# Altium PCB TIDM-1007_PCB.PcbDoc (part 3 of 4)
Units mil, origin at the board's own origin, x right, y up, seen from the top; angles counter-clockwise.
Board outline 9645.67 x 3346.46 mil, 6 copper layers (Top Layer, Signal Layer 1, Signal Layer 2, Signal Layer 3, Signal Layer 4, Bottom Layer), stack 60.2 mil thick; 189 components, 109 nets, 620 pads, 278 vias.
Unrouted connection lines stored in the file: 5.
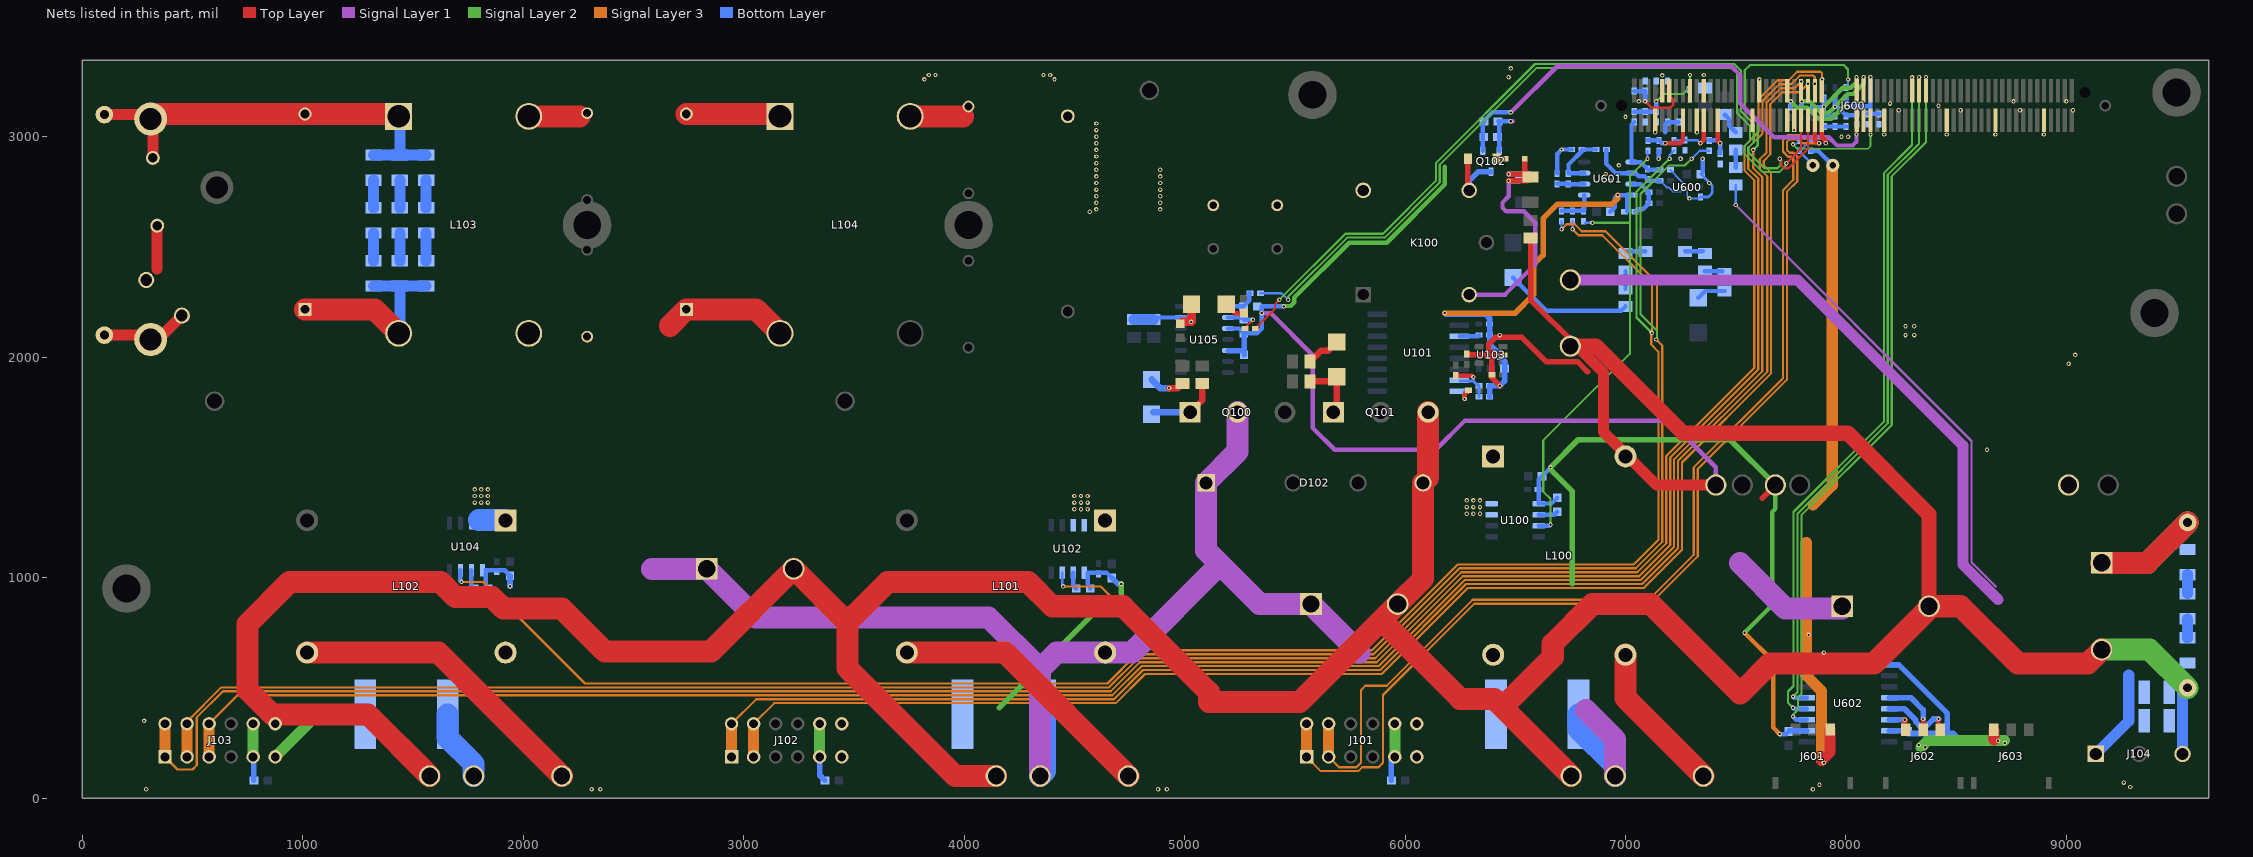
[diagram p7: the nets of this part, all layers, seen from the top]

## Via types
v1: diameter 20, hole 10, Top Layer to Bottom Layer, 278 vias

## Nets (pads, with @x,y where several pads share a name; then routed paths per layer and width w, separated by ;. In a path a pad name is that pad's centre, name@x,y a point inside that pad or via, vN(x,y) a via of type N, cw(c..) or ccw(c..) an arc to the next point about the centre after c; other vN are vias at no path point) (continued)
GAN_F3: J103.3 R626.2 | length 10076.2
  Signal Layer 2 w10: v1(7580,2940) 7600,2960 7600,3065.1 7541.38,3123.72 7541.38,3301.38 7565.49,3325.49 7989.5,3325.49 8009.72,3305.27 v1(8009.72,3259.37)
  Signal Layer 3 w10: J103.3@575,337 704.38,466.38 4672.21,466.38 4804.34,598.5 5879.61,598.5 6269.61,988.5 7068.5,988.5 7220.63,1140.63 7220.63,1537.02 7620,1936.39 7620,2817.44 7580,2857.44 v1(7580,2940)
  Signal Layer 3 w50: J103.3@575,187 J103.3@575,337
  Bottom Layer w10: R626.2@8000,3223.62 8009.72,3233.34 v1(8009.72,3259.37)
HVBUS: C100.1 C101.1 C102.1 C103.1 C104.2 C105.2 C106.2 C117.2 C126.2 D102.1 J104.1 L100.4 L101.2 L102.2 Q100.2 R129.2 R602.2 TP100.1 TP104.1 TP107.1 TP110.1 TP600.1 | length 13405.7
  Top Layer w100: C100.1@9160,1066.85 9366.85,1066.85 TP100.1@9550,1250
  Signal Layer 1 w10: v1(7500,2690) 8570,1620 8570,1070 8680,960
  Signal Layer 1 w50: TP600.1@6750,2350 7780,2350 8530,1600 8530,1060 8690,900
  Signal Layer 1 w100: 2585.28,1040 C103.1@2833.15,1040 3053.15,820 4110,820 4345,585 ; TP107.1@4345,100 4345,585 ; Q100.2@5240,1750 5240,1572.13 D102.1@5097.87,1430 5097.87,1123.15 5161.02,1060 ; 5793.15,660 C102.1@5573.15,880 5341.02,880 5161.02,1060 ; 6820,400 6953.45,266.55 TP104.1@6953.45,100 ; 7520,1065.28 7725.28,860 C101.1@7983.15,860 ; 4345,585 4420,660 L101.2@4640,660 4761.02,660 5161.02,1060
  Signal Layer 2 w100: C100.1@9160,1066.85 9366.85,1066.85 TP100.1@9550,1250
  Bottom Layer w10: v1(7500,2690) R602.2@7500,2780
  Bottom Layer w50: J104.1@9133.15,200 9282.91,349.76 9282.91,557.09
  Bottom Layer w100: C106.2@1657.01,380 1657.01,272.99 1775,155 TP110.1@1775,100 ; TP107.1@4345,100 4367.01,122.01 C117.2@4367.01,380 ; C126.2@6787.01,380 6787.01,312.99 6953.45,146.55 TP104.1@6953.45,100
L100_CS: R600.1 R627.2 U100.7 | length 2162.5
  Signal Layer 2 w10: v1(6660,1240) 6660,1357.1 6627.1,1390 6627.1,1622.37 7020,2015.28 7020,2610 ; v1(6850,2610) 7020,2610 ; v1(7100,2900) 7020,2820 7020,2610
  Bottom Layer w10: R627.2@6816.38,2610 v1(6850,2610) ; v1(7100,2900) R600.1@7100,2934.57
  Bottom Layer w20: U100.7@6607.28,1235 6655,1235 v1(6660,1240)
L101_CS: R603.1 R628.2 U102.7 | length 5690
  Signal Layer 2 w10: v1(7120,2110) 7050,2180 7050,2750 v1(7200,2900)
  Signal Layer 3 w10: v1(4450,960) 4620,960 4910,670 5850,670 6240,1060 7038.89,1060 7149.13,1170.24 7149.13,2025.12 7117.13,2057.13 7117.13,2107.13 v1(7120,2110) 7120,2327.87 6895,2552.87 6787.13,2552.87 v1(6760,2580)
  Bottom Layer w10: U102.7@4445,1022.72 4445,965 v1(4450,960) ; v1(6760,2580) R628.2@6760,2616.38 ; v1(7200,2900) 7200,2916.45 R603.1@7220,2936.45
L102_CS: R608.1 R629.2 U104.7 | length 8815.7
  Signal Layer 2 w10: v1(7140,2080) 7142.87,2082.87 7142.87,2119.47 7067.87,2194.47 7067.87,2739.69 7198.19,2870 7270,2870 v1(7300,2900)
  Signal Layer 3 w10: v1(1720,980.32) 1819.68,980.32 2280,520 4650,520 4782.13,652.13 5857.4,652.13 6247.4,1042.13 7046.29,1042.13 7167.01,1162.84 7167.01,2052.99 v1(7140,2080) ; v1(6710,2580) 6732.87,2602.87 6769.47,2602.87 6801.6,2570.75 6909.25,2570.75 7142.87,2337.13 v1@7142.87,2082.87
  Bottom Layer w10: v1(6710,2580) R629.2@6710,2616.38 ; v1(7300,2900) 7336.38,2936.38 R608.1@7380,2936.38
  Bottom Layer w20: U104.7@1715,1033.03 1715,985.32 v1(1720,980.32)
NetC107_1: C107.1 C110.1 L103.3 L104.2 | length 575.6
  Top Layer w100: 2665.28,2142.36 C110.1@2740,2217.09 3055.51,2217.09 L104.2@3164.72,2107.87
NetC109_1: C109.1 F100.1 L103.2 R105.2 R106.2 R107.2 RV100.2 | length 1116.4
  Top Layer w50: 339.8,2399.8 RV100.2@339.8,2596.45
  Top Layer w100: C109.1@1010,2217.09 1325.51,2217.09 L103.2@1434.72,2107.87
  Bottom Layer w50: R106.2@1320,2322.91 R107.2@1440,2322.91 ; L103.2@1440,2113.15 R107.2@1440,2322.91 ; R105.2@1560,2322.91 R107.2@1440,2322.91
NetC109_2: C109.2 L103.1 pad.0@310,3080 R111.1 R112.1 R113.1 RV100.1 TP103.1 | length 1889.4
  Top Layer w50: TP103.1@100,3100 pad.0@290,3100 ; RV100.1@320.2,2903.55 pad.0@320.2,3069.8
  Top Layer w100: pad.0@310,3080 332.91,3102.91 C109.2@1010,3102.91 L103.1@1423.94,3102.91
  Bottom Layer w50: R112.1@1320,2917.09 R113.1@1440,2917.09 ; L103.1@1440,3086.85 R113.1@1440,2917.09 ; R111.1@1560,2917.09 R113.1@1440,2917.09
NetC110_2: C110.2 C112.2 L103.4 L104.1 | length 644.2
  Top Layer w100: L103.4@2025.28,3092.13 2255.51,3092.13 ; C110.2@2740,3102.91 L104.1@3153.94,3102.91
NetC113_1: C113.1 C114.2 K100.2 L104.4 RT100.1 RT101.1 | length 240.2
  Top Layer w100: L104.4@3755.28,3092.13 3995.51,3092.13
  other v1: 4570,2660 4600,2670 4890,2670 4600,2700 4890,2700 4600,2730 4890,2730 4600,2760 4890,2760 4600,2790 4890,2790 4600,2820 4890,2820 4600,2850 4890,2850 4600,2880 4600,2910 4600,2940 4600,2970 4600,3000 4600,3030 4600,3060 3820,3260 4410,3260 3840,3280 3870,3280 4360,3280 4390,3280
NetC116_1: C116.1 U100.6 | length 88.3
  Bottom Layer w20: U100.6@6607.28,1285 6676.5,1285 C116.1@6690,1298.5
NetC124_1: C124.1 R117.1 R124.2 U101.15 | length 253.2
  Top Layer w20: R117.1@6230,1916.38 6303.62,1916.38 v1(6310,1910)
  Bottom Layer w14: U101.15@6250.01,1892 6310,1892 ; v1(6310,1910) 6310,1892 ; C124.1@6331.38,1875 C124.1@6336.38,1870 ; R124.2@6336.38,1820 C124.1@6336.38,1870 ; 6310,1892 6332,1870 C124.1@6336.38,1870
NetC125_1: C125.1 U102.6 | length 78.3
  Bottom Layer w20: U102.6@4495,1022.72 4495,963.51 C125.1@4508.5,950
NetC127_1: C127.1 U101.11 | length 91.4
  Bottom Layer w20: U101.11@6247.01,2095 6331.38,2095 C127.1@6336.38,2100
NetC134_1: C134.1 U104.6 | length 69.2
  Bottom Layer w20: C134.1@1765,963.82 U104.6@1765,1033.03
NetC135_1: C135.1 C137.1 C138.2 D107.1 U105.13 | length 392.3
  Top Layer w20: C138.2@4980,2151.5 C138.2@4988.5,2160
  Top Layer w39.37: C138.2@4988.5,2160 v1(5030,2160) 5031.26,2161.26 D107.1@5031.26,2240
  Bottom Layer w20: C135.1@4870,2180 U105.13@4982.72,2180 5010,2180 v1(5030,2160)
  Bottom Layer w50: C137.1@4770,2170 C135.1@4860,2170
NetC139_1: C139.1 R127.1 U105.1 | length 144.2
  Bottom Layer w20: U105.1@5197.28,2230 C139.1@5267.05,2230 5292.48,2255.43 5292.48,2290 R127.1@5296.38,2290
NetC140_1: C140.1 R128.1 U105.2 | length 172.1
  Top Layer w10: R128.1@5273.27,2130 5273.27,2133.27 v1(5310,2170)
  Bottom Layer w20: U105.2@5197.28,2180 5259.84,2180 C140.1@5268.35,2171.5 5269.84,2170 v1(5310,2170)
NetC601_1: C601.1 J600.15 R600.2 | length 261.2
  Top Layer w20: v1(7180.39,2970) 7248.19,2970 7260.91,2982.72 J600.15@7260.91,3073.94
  Bottom Layer w20: R600.2@7101.81,2983.62 C601.1@7151.81,2983.62 7165.43,2970 v1(7180.39,2970)
NetC603_2: C603.2 J600.12 R604.1 | length 310.5
  Top Layer w12: v1@7090,3160 7118.19,3131.81 7203.81,3131.81 7216.13,3144.13 7216.13,3167.64 7197.91,3185.85 J600.12@7197.91,3207.8
  Bottom Layer w20: R604.1@7040,3206.38 C603.2@7090,3206.38 v1@7090,3160
  other v1: 7089,3160
NetC604_1: C604.1 J600.21 R603.2 | length 236
  Top Layer w20: v1(7340,2970) 7355.39,2985.39 J600.21@7355.39,3073.94
  Bottom Layer w10: R603.2@7220,2983.69 7326.31,2983.69 v1(7340,2970)
NetC607_1: C607.1 J600.25 R608.2 | length 210.8
  Top Layer w20: J600.25@7418.39,3073.94 7418.39,2981.61 v1(7430,2970)
  Bottom Layer w20: R608.2@7380,2983.62 7416.38,2983.62 v1(7430,2970) C607.1@7430,2923.62
NetC608_1: C608.1 J600.18 R611.1 R613.2 | length 370.2
  Signal Layer 2 w10: v1(7140,3160) 7173.51,3193.51 7260,3193.51 7292.5,3226.01 v1(7292.5,3280)
  Bottom Layer w20: R611.1@7040,3113.62 R613.2@7090,3113.62 C608.1@7140,3113.62 7140,3150
NetC611_1: C611.1 J600.58 R618.1 R621.1 R631.2 | length 395.3
  Signal Layer 2 w20: v1(7900,3135.91) 7985.75,3221.65 8021.65,3221.65 8048,3248 v1(8048,3270)
  Bottom Layer w20: R618.1@7847.97,3133.62 v1@7897.72,3133.62 ; C611.1@7900,3095.43 v1(7900,3135.91) R621.1@7900,3176.38 ; C611.1@7901.81,3093.62 R631.2@7950,3093.62
NetC612_1: C612.1 J600.60 R620.1 R625.1 R632.2 | length 570
  Signal Layer 2 w20: v1(7800,3160) 7818.47,3160 7818.76,3159.71 7836.77,3159.71 7888.45,3108.03 7922.13,3108.03 v1(7950,3135.91) 8007.87,3193.78 8033.2,3193.78 8080,3240.58 v1(8080,3270)
  Bottom Layer w20: R620.1@7800,3135.65 v1(7800,3160) ; R625.1@7950,3176.38 v1(7950,3135.91) 7960.55,3135.91 8000,3096.46 8042.84,3096.46 R632.2@8050,3103.62
NetC613_1: C613.1 J600.62 R624.1 R626.1 R633.2 | length 685.2
  Signal Layer 2 w20: v1(7750,3160) 7778.16,3131.84 7825.23,3131.84 7876.91,3080.16 7933.67,3080.16 7987.61,3134.09 v1(8001.81,3134.09)
  Bottom Layer w20: R624.1@7750,3135.65 v1(7750,3160) ; R626.1@8001.81,3174.57 v1(8001.81,3134.09) 8004.96,3137.24 8108.24,3137.24 ; C613.1@8100,3103.62 R633.2@8150,3103.62 ; C613.1@8111,3114.62 v1(8111,3270)
NetC614_1: C614.1 R619.1 R622.1 U601.7 | length 261.1
  Bottom Layer w20: C614.1@6803.62,2936.22 6741.38,2873.97 6741.38,2835 U601.7@6812.72,2835 ; C614.1@6803.62,2941.81 R619.1@6866.38,2941.81
NetD100_1: D100.1 R102.2 | length 132.9
  Bottom Layer w20: D100.1@7330,2268.74 7361.26,2300 R102.2@7450,2300
NetD101_1: D101.1 R103.1 | length 164.3
  Top Layer w29.53: v1(4930,1860) 4970,1860 R103.1@4990,1880
  Bottom Layer w29.53: D101.1@4850,1898.74 4888.74,1860 v1(4930,1860)
NetD101_2: D101.2 Q100.1 R104.1 | length 319
  Top Layer w29.53: Q100.1@5025,1750 5080,1805 R104.1@5080,1880
  Bottom Layer w29.53: D101.2@4858.74,1750 Q100.1@5025,1750
NetD103_1: D103.1 R114.1 | length 156.8
  Top Layer w29.53: R114.1@5570,1980 5620,2030 5651.26,2030 D103.1@5690,2068.74
NetD103_2: D103.2 Q101.1 R115.1 | length 245
  Top Layer w29.53: R115.1@5570,1890 D103.2@5668.74,1890 ; Q101.1@5690,1765 D103.2@5690,1911.26
NetD104_1: D104.1 R119.2 | length 581.7
  Bottom Layer w20: D104.1@6490,2361.26 6490,2360 6640,2210 6980,2210 R119.2@7000,2230
NetD105_1: D105.1 K100.5 Q102.3 | length 298.3
  Top Layer w25: K100.5@6285.53,2761.48 D105.1@6285.53,2900
  Bottom Layer w25: K100.5@6290.79,2756.22 6290.79,2799.53 6332.56,2841.3 Q102.3@6390,2841.3
NetD105_2: D105.2 D106.2 | length 42.2
  Top Layer w25: D105.2@6414.47,2900 D106.2@6456.69,2900
NetD106_1: D106.1 K100.4 R118.1 R120.1 | length 1222.9
  Top Layer w25: v1(6470,2800) 6552.6,2800 R118.1@6569.69,2817.09 ; v1(6470,2830) 6556.77,2830 6543.31,2843.46 D106.1@6543.31,2900
  Signal Layer 1 w20: K100.4@6290.79,2283.78 6453.78,2283.78 6590,2420 6590,2610.58 6538.45,2662.13 6458.45,2662.13 6442.13,2678.45 6442.13,2701.55 6470,2729.42 v1(6470,2800)
  Bottom Layer w25: v1(6470,2800) R120.1@6517.17,2800 ; v1(6470,2830) R120.1@6521.34,2830
NetD107_2: D107.2 R126.1 | length 98.4
  Top Layer w20: D107.2@5188.74,2240 5230.24,2198.5 R126.1@5270,2198.5
NetF100_2: F100.2 pad.0@310,2080 TP101.1 | length 388.2
  Top Layer w50: TP101.1@100,2100 363.07,2100 F100.2@451.53,2188.47
NetJ101_5: J101.5 R132.1 | length 242.1
  Signal Layer 2 w50: J101.5@5953.45,187 J101.5@5953.45,337
  Bottom Layer w25: R132.1@5938.5,80 J101.5@5938.5,172.06
NetJ102_5: J102.5 R133.1 | length 266.7
  Signal Layer 2 w50: J102.5@3345,187 J102.5@3345,337
  Bottom Layer w25: J102.5@3345,187 3345,103.5 R133.1@3368.5,80
NetJ103_5: J103.5 R134.1 | length 253.5
  Signal Layer 2 w50: J103.5@775,187 J103.5@775,337
  Bottom Layer w25: R134.1@778.5,80 J103.5@778.5,183.5
NetJ600_61: J600.61 R630.2 | length 454.7
  Signal Layer 2 w7.87: v1(7760,2965) 7779.25,2945.75 8100,2945.75 8111.5,2957.25 v1(8111.5,3010)
  Bottom Layer w7.87: v1(7760,2965) 7771.38,2965 R630.2@7790,2983.62
NetJ602_1: J602.1 U602.14 | length 109.9
  Top Layer w25: J602.1@8266.41,314.46 v1(8266.41,355)
  Bottom Layer w25: U602.14@8197.01,355 v1(8266.41,355)
NetJ602_2: J602.2 U602.12 | length 266.2
  Top Layer w20: J602.2@8350,309.61 v1(8350,358.59)
  Bottom Layer w25: U602.12@8197.01,455 8295,455 8350,400 v1(8350,358.59)
NetJ602_3: J602.3 U602.13 | length 314.3
  Top Layer w20: J602.3@8420,318.35 v1(8420,358.59)
  Bottom Layer w25: U602.13@8197.01,405 8265,405 8317.13,352.87 8317.13,344.97 8336.38,325.72 8363.62,325.72 8396.49,358.59 v1(8420,358.59)
NetL100_1: L100.1 U100.3 U100.4
  other v1: 6280,1290 6310,1290 6340,1290 6280,1320 6310,1320 6340,1320 6280,1350 6310,1350 6340,1350
NetL101_1: L101.1 U102.3 U102.4
  other v1: 4500,1310 4530,1310 4560,1310 4500,1340 4530,1340 4560,1340 4500,1370 4530,1370 4560,1370
NetL102_1: L102.1 U104.3 U104.4 | length 110
  Bottom Layer w100: 1800,1260.32 L102.1@1910,1260.32
  other v1: 1780,1340 1810,1340 1840,1340.32 1780,1370 1810,1370 1840,1370 1780,1400 1810,1400 1840,1400
NetR100_2: R100.2 R101.1 | length 80
  Bottom Layer w20: R100.2@7270,2480 R101.1@7350,2480
NetR101_2: R101.2 R102.1 | length 80
  Bottom Layer w20: R101.2@7360,2390 R102.1@7440,2390
NetR105_1: R105.1 R108.2 | length 125.8
  Bottom Layer w50: R105.1@1560,2437.09 R108.2@1560,2562.91
NetR106_1: R106.1 R109.2 | length 125.8
  Bottom Layer w50: R106.1@1320,2437.09 R109.2@1320,2562.91
NetR107_1: R107.1 R110.2 | length 125.8
  Bottom Layer w50: R107.1@1440,2437.09 R110.2@1440,2562.91
NetR108_1: R108.1 R111.2 | length 125.8
  Bottom Layer w50: R108.1@1560,2677.09 R111.2@1560,2802.91
NetR109_1: R109.1 R112.2 | length 125.8
  Bottom Layer w50: R109.1@1320,2677.09 R112.2@1320,2802.91
NetR110_1: R110.1 R113.2 | length 125.8
  Bottom Layer w50: R110.1@1440,2677.09 R113.2@1440,2802.91
NetR116_1: R116.1 U101.16 | length 77.6
  Top Layer w20: v1(6270,1810) 6270,1831.62 R116.1@6288.38,1850
  Bottom Layer w20: v1(6270,1810) U101.16@6270,1840
NetR119_1: R119.1 R121.2 | length 80
  Bottom Layer w20: R119.1@7000,2310 R121.2@7000,2390
NetR121_1: R121.1 R123.2 | length 80
  Bottom Layer w20: R121.1@7010,2480 R123.2@7090,2480
NetR129_1: R129.1 R130.2 | length 85.8
  Bottom Layer w50: R130.2@9550,927.09 R129.1@9550,1012.91
NetR130_1: R130.1 R131.2 | length 85.8
  Bottom Layer w50: R131.2@9550,727.09 R130.1@9550,812.91
NetR601_1: R601.1 R606.1 R611.2 U601.1 | length 325.1
  Bottom Layer w20: R611.2@7040,3066.38 7027.28,3053.66 U601.1@7027.28,2885 7068.62,2885 R606.1@7100,2853.62 ; R606.1@7103.62,2850 R601.1@7156.38,2850
NetR601_2: R601.2 U600.4 | length 91.7
  Bottom Layer w7.87: R601.2@7203.62,2850 7228,2825.62 7228,2823.07 7260.31,2790.75 U600.4@7260.31,2781.81
NetR602_1: R602.1 R605.2 | length 80
  Bottom Layer w20: R602.1@7500,2860 R605.2@7500,2940
NetR605_1: R605.1 R607.2 | length 100.7
  Bottom Layer w20: R607.2@7450,3100 7470,3080 7470,3050 R605.1@7500,3020
NetR606_2: R606.2 R610.2 R619.2 U600.3 U601.2 | length 468.7
  Bottom Layer w7.87: R610.2@7156.38,2800 7186.38,2770 7195.97,2770 7215.97,2750 7250,2750 U600.3@7260.31,2760.31
  Bottom Layer w20: R619.2@6913.62,2941.81 6913.62,2876.38 6955,2835 U601.2@7027.28,2835 7045,2835 7060,2820 7086.38,2820 R606.2@7100,2806.38 7106.38,2800 R610.2@7156.38,2800
NetR612_1: R612.1 R614.1 R615.2 U601.3 | length 222.9
  Bottom Layer w20: U601.3@7027.28,2785 7068.54,2785 7105.35,2748.19 R612.1@7106.38,2748.19 R614.1@7106.38,2698.19 7078.19,2670 7053.62,2670 R615.2@7043.62,2660
NetR622_2: R622.2 R623.1 U601.6 | length 121.3
  Bottom Layer w20: R623.1@6690,2786.38 R622.2@6740,2786.38 ; R622.2@6741.38,2785 U601.6@6812.72,2785
NetR627_1: R627.1 R628.1 R629.1 U601.5 | length 168.7
  Bottom Layer w20: R629.1@6710,2663.62 R628.1@6760,2663.62 R627.1@6810,2663.62 ; R627.1@6812.72,2666.34 U601.5@6812.72,2735
PFCG_1H: J101.1 J600.53 | length 4906.4
  Top Layer w20: J600.53@7859.33,3073.94 7859.33,2982.32 7871.65,2970 v1(7878.19,2970)
  Signal Layer 3 w10: J101.1@5553.45,187 5618.32,122.13 5787.4,122.13 5805.28,140 5880,140 5900,160 5900,467.22 6314.04,881.26 7112.93,881.26 7327.87,1096.21 7327.87,1492.6 7732.09,1896.81 7732.09,2750 7779.21,2797.13 7779.21,2910.79 7762.74,2927.26 7744.83,2927.26 7732.09,2940 7732.09,2976.78 7743.7,2988.39 7785.39,2988.39 7803.78,2970 v1(7878.19,2970)
  Signal Layer 3 w50: J101.1@5553.45,187 J101.1@5553.45,337
PFCG_1L: J101.2 J600.55 | length 4846.4
  Top Layer w20: J600.55@7890.83,3073.94 7890.83,2999.17 7908.45,2981.55 v1(7908.45,2970)
  Signal Layer 3 w10: J101.2@5653.45,187 5700.45,140 5780,140 5800,160 5800,489.13 5820,509.13 5916.63,509.13 6306.63,899.13 7105.52,899.13 7310,1103.61 7310,1500 7714.21,1904.21 7714.21,2757.4 7761.34,2804.53 7761.34,2903.38 7755.34,2909.38 7737.43,2909.38 7714.21,2932.6 7714.21,2984.18 7736.29,3006.26 7792.8,3006.26 7806.18,2992.87 7887.66,2992.87 7908.45,2972.09 v1(7908.45,2970)
  Signal Layer 3 w50: J101.2@5653.45,187 J101.2@5653.45,337
PFCG_2H: J102.1 J600.50 | length 7185.6
  Signal Layer 3 w10: J102.1@2945,337 3056.5,448.5 4679.61,448.5 4811.74,580.63 5887.02,580.63 6277.02,970.63 7075.91,970.63 7238.5,1133.23 7238.5,1529.61 7642.72,1933.83 7642.72,2820 7609.25,2853.46 7609.25,2897.4 7639.25,2927.4 7639.25,3154.53 7704.6,3219.87 7766.87,3219.87 v1(7797,3250)
  Signal Layer 3 w50: J102.1@2945,187 J102.1@2945,337
PFCG_2L: J102.2 J600.52 | length 7112.5
  Signal Layer 3 w10: J102.2@3045,337 3138.63,430.63 4687.87,430.63 4820,562.76 5894.42,562.76 6284.42,952.76 7083.31,952.76 7256.38,1125.82 7256.38,1522.21 7660.59,1926.42 7660.59,2837.06 7627.13,2870.53 7627.13,2890 7657.13,2920 7657.13,3147.13 7712,3202 7790,3202 v1(7828,3240)
  Signal Layer 3 w50: J102.2@3045,187 J102.2@3045,337
PFCG_3H: J103.1 J600.54 | length 10093.5
  Signal Layer 3 w10: J103.1@375,187 432.12,129.88 500,129.88 519.37,149.25 519.37,365.86 637.76,484.25 4664.81,484.25 4796.93,616.38 5872.21,616.38 6262.21,1006.38 7061.1,1006.38 7202.76,1148.03 7202.76,1544.42 7602.13,1943.79 7602.13,2810.04 7557.13,2855.04 7557.13,2949.47 7621.38,3013.73 7621.38,3161.93 7697.19,3237.75 7750.62,3237.75 7790,3277.13 7852.87,3277.13 7859,3271 v1(7859,3240)
  Signal Layer 3 w50: J103.1@375,187 J103.1@375,337
PFCG_3L: J103.2 J600.56 | length 9800.5
  Signal Layer 3 w10: J103.2@475,337 475,346.77 630.35,502.13 4657.4,502.13 4789.53,634.25 5864.81,634.25 6254.81,1024.25 7053.7,1024.25 7184.88,1155.44 7184.88,1551.83 7584.25,1951.2 7584.25,2802.63 7539.25,2847.63 7539.25,2956.88 7603.5,3021.13 7603.5,3169.34 7689.79,3255.62 7740,3255.62 7779.38,3295 7884.74,3295 7892,3287.74 v1(7892,3260)
  Signal Layer 3 w50: J103.2@475,187 J103.2@475,337
PGND: C100.2 C101.2 C102.2 C103.2 C104.1 C105.1 C106.1 C111.2 C115.2 C116.2 C117.1 C118.2 C119.2 C120.2 C121.2 C122.1 C123.2 C124.2 C125.2 C126.1 C127.2 C128.2 C129.1 C130.2 C131.2 C132.2 C133.2 C134.2 C136.2 C139.2 C140.2 C600.1 C601.2 C602.2 C603.1 C604.2 C605.1 C606.2 C607.2 C608.2 C609.2 C610.2 C611.2 C612.2 C613.2 C614.2 C615.1 C617.2 D102.4 J101.6 J102.6 J103.6 J104.3 J600.7 J600.10 J600.19 J600.22 J600.35 J600.38 J600.46 J600.47 J600.65 J600.83 J600.97 J600.111 J601.3 L100.2 pad.3 Q101.3 Q102.2 R122.1 R124.1 R131.1 R609.1 R613.1 R615.1 R616.1 R617.1 R623.2 R631.1 R632.1 R633.1 TP102.1 TP106.1 TP109.1 TP112.1 TP602.1 TP606.1 TP609.1 U100.5 U101.9 U102.5 U103.2 U104.5 U105.3 U105.5 U600.2 U601.4 U602.2 U602.8 | length 35289.8
  Top Layer w25: C131.2@6280,2013.62 6283.62,2010 U103.2@6444.13,2010 ; 6380,2020 6380,2060 6410,2090 6530,2090 6640,1980 6782.13,1980 6828.51,1933.62 ; 6393.88,2006.12 C133.2@6393.88,1920 6393.88,1906.12 v1(6430,1870) ; C122.1@6570,2540 6570,2260 TP602.1@6780,2050 ; 7619.63,1359.63 TP609.1@7680,1420
  Top Layer w50: TP602.1@6780,2050 6900,1930 6900,1660 7140,1420 TP606.1@7410,1420 ; 7890,170 7928.74,208.74 J601.3@7928.74,311.02
  Top Layer w70: TP602.1@6750,2050 6780,2050 6865.94,2050 7260.67,1655.28 8008.17,1655.28 8376.85,1286.59 C101.2@8376.85,870
  Top Layer w100: TP112.1@1575,100 1295,380 860,380 750,490 750,790 940,980 1624.33,980 1691.89,912.44 1857.56,912.44 1910,860 2174.72,860 2370,664.72 2851.57,664.72 C103.2@3226.85,1040 3470,796.85 ; TP109.1@4145,100 3960,100 3470,590 3470,796.85 ; Q101.3@6105,1750 6105,1452.87 D102.4@6082.13,1430 6082.13,995.28 C102.2@5966.85,880 5893.43,806.57 ; TP106.1@6753.45,100 6441.72,411.72 ; C100.2@9160,673.15 9096.85,610 8780,610 8520,870 C101.2@8376.85,870 8376.85,860 8126.85,610 7655.28,610 7520,474.72 7114.72,880 6850,880 6670,700 6670,640 6441.72,411.72 ; 3470,796.85 3653.15,980 4290,980 4400,870 4720,870 5110,480 5110,434.72 5521.57,434.72 5893.43,806.57 ; 5893.43,806.57 6250,450 6403.45,450 6441.72,411.72
  Signal Layer 1 w20: v1(5350,2200) 5390.58,2200 5581.75,2008.83 5581.75,1678.83 5680.95,1579.63 6139.05,1579.63 6271.55,1712.13 7198.45,1712.13 7410,1500.58 TP606.1@7410,1420 ; v1(6480,3070) v1@6487.87,3070
  Signal Layer 2 w20: v1(5450,2230) 5452.13,2232.13 5481.55,2232.13 5497.87,2248.45 5497.87,2270.25 5746.88,2519.25 5916.88,2519.25 6180.75,2783.12 6180.75,2863.12 ; v1(7540,750) 7665,875 7665,1296.77 7680,1311.77 TP609.1@7680,1420
  Signal Layer 2 w25: 4160,410 4611.13,861.13 4712.38,861.13 v1@4712.38,971.13 ; 6759,971.34 6759,1391.03 6660,1490.03 v1(6660,1500) 6785.28,1625.28 7474.72,1625.28 TP609.1@7680,1420
  Signal Layer 2 w50: J103.6@875,187 1048,360
  Signal Layer 2 w100: C100.2@9160,673.15 9376.85,673.15 TP102.1@9550,500
  Signal Layer 3 w20: v1(7540,750) 7670,620 7670,320 v1(7700,290)
  Signal Layer 3 w25: v1(6180,2200) 6500,2200 6583.19,2283.19 6583.19,2419.63 6626,2462.44 6626,2628.19 6691.81,2694 6940,2694 6965,2719 v1(6965,2735)
  Signal Layer 3 w50: TP609.1@7680,1400 TP609.1@7680,1420 ; 7820,1160 7820,556.1 7890,486.1 7890,170 ; 7850,1330 7937.87,1417.87 7937.87,2867.87 pad.3@7940,2870
  Bottom Layer w7.87: U600.2@7280,2758.19 7280,2730 v1(7290,2720) 7333.62,2720 C602.2@7340,2726.38
  Bottom Layer w12: C602.2@7340,2726.38 7376.38,2726.38 7391.88,2741.88 7391.88,2746.13 7393.87,2748.12 7393.87,2776.13 v1(7380,2790) 7380,2791.5 C600.1@7341.5,2830 ; 7873.62,2936.38 7878.19,2931.81
  Bottom Layer w20: 1830,1020.32 1830,961.81 C134.2@1841.5,950.32 ; 1830,1033.03 1915.79,1033.03 C132.2@1940,1008.82 ; C125.2@4571.5,950 4571.5,957.2 4560,968.7 4560,1022.72 4645.79,1022.72 C123.2@4670,998.5 ; U105.3@5197.28,2130 5246.85,2130 C140.2@5268.35,2108.5 5328.5,2108.5 5350,2130 v1(5350,2200) 5350,2230 v1(5450,2230) ; R122.1@6422.95,3070 v1(6480,3070) ; Q102.2@6427.4,2935.79 R122.1@6427.4,3062.64 ; U100.5@6607.28,1335 U100.5@6607.28,1336.06 ; v1(6660,1500) 6660,1498.5 C115.2@6621.5,1460 6607.28,1445.79 U100.5@6607.28,1336.06 ; C116.2@6690,1361.5 6664.57,1336.06 U100.5@6607.28,1336.06 ; R623.2@6690,2833.62 6690,2921.81 v1(6710,2941.81) C614.2@6756.38,2941.81 ; C605.1@6931.5,2660 6951.5,2680 6951.5,2721.5 v1(6965,2735) U601.4@7007.28,2735 ; R615.1@7007.28,2661.22 U601.4@7007.28,2735 ; U601.4@7027.28,2735 U601.4@7007.28,2735 ; v1(7150,2900) 7151.81,2901.81 C601.2@7151.81,2936.38 ; 7180,3020 7180,3056.38 C609.2@7190,3066.38 R616.1@7240,3066.38 ; v1@7248.19,2901.81 v1(7250,2900) ; C600.1@7350,2838.5 v1(7350,2900) ; 7520,474.72 7650.28,605 U602.8@7822.99,605 ; v1(7700,290) 7728.5,290 C615.1@7740,301.5 ; C617.2@7840,2936.38 7873.62,2936.38 ; 7878.19,2931.81 pad.3@7940,2870 ; C611.2@7901.81,3046.38 C612.2@8001.81,3046.38
  Bottom Layer w25: v1(1940,960.32) C132.2@1940,1008.82 ; C123.2@4670,998.5 4697.25,971.26 v1(4712.5,971.26) ; U105.5@5197.28,2030 C136.2@5260.02,2030 ; C140.2@5268.35,2108.5 5270,2106.85 C136.2@5270,2011.5 ; v1(6180,2200) 6185,2195 U101.9@6247.01,2195 6365,2195 6383.62,2176.38 C128.2@6383.62,2150 C127.2@6383.62,2100 C129.1@6383.62,2050 ; R124.1@6383.62,1820 C124.2@6383.62,1866.12 ; C124.2@6383.62,1870 v1(6430,1870) 6451.5,1891.5 C119.2@6451.5,1948.98 6451.5,1982.13 C118.2@6433.62,2000 6422.5,2011.12 6422.5,2021.22 6421.53,2021.22 C129.1@6392.75,2050 ; C615.1@7743.5,305 U602.2@7822.99,305
  Bottom Layer w50: J104.3@9526.85,200 TP102.1@9526.85,476.85
  other v1: 290,40 2310,40 2350,40 4880,40 4920,40 7850,40 9290,50 7880,60 9260,70 7900,160 7880,180 280,350 7900,660 7830,740 8640,1580 9010,1970 9040,2010 6430,2100 8270,2100 8310,2100 8270,2140 8310,2140 6930,2800 6910,2830 6970,2870 7980,3000 8010,3000 8174,3010 8457.5,3010 8678,3010 8898,3010 7135,3020 7324,3020 7765,3030.63 7000,3090 8240,3120 8520,3120 8790,3120 9030,3120 8420,3140 8200,3150 7060,3160 8760,3160 9000,3160 7607.5,3260 6470,3270 7167,3278 7355.5,3280 6480,3310
PRI_FAULT: J600.74 U602.4 | length 3166.4
  Signal Layer 2 w10: v1(7760,410) 7737.13,432.87 7737.13,482.87 7762.13,507.87 7762.13,1297.4 8172.13,1707.4 8172.13,2834.81 8300,2962.68 v1(8300,3268.74)
  Bottom Layer w20: v1(7760,410) 7765,405 U602.4@7822.99,405
PWM1A: J600.49 R127.2 | length 3546.2
  Top Layer w10: v1(7730,2880) 7796.34,2946.34 J600.49@7796.34,3073.94
  Signal Layer 2 w10: v1(5470,2260) 5470,2274.72 5737.4,2542.13 5907.4,2542.13 6157.87,2792.6 6157.87,2872.6 6597.4,3312.13 7486.1,3312.13 7505.63,3292.6 7505.63,3108.91 7564.25,3050.29 7564.25,2981.88 7539.25,2956.88 7539.25,2923.12 7623.12,2839.25 7696.88,2839.25 7730,2872.37 v1(7730,2880)
  Bottom Layer w10: R127.2@5343.62,2290 5440,2290 v1(5470,2260)
PWM1B: J600.51 R128.2 | length 3711.6
  Top Layer w10: R128.2@5320.51,2130 5410,2219.49 5410,2240 v1(5430,2260) ; v1(7700,2900) 7707.13,2892.87 7707.13,2870.53 7720.53,2857.13 7739.47,2857.13 7827.83,2945.49 J600.51@7827.83,3073.94
  Signal Layer 2 w10: v1(5430,2260) 5730,2560 5900,2560 6140,2800 6140,2880 6590,3330 7493.5,3330 7523.5,3300 7523.5,3116.31 7582.13,3057.69 7582.13,2974.47 7557.13,2949.47 7557.13,2930.53 7630.53,2857.13 7689.47,2857.13 7702.87,2870.53 7702.87,2897.13 v1(7700,2900)
PWM_DEBUG: C617.1 pad.4 R630.1 | length 159.2
  Bottom Layer w10: R630.1@7790,2932 7790,2933.62 C617.1@7840,2983.62
  Bottom Layer w12: R630.1@7790,2932 7850,2872 pad.4@7850,2870
RELAY_CTRL: C120.1 J600.57 Q102.1 R122.2 | length 2186.8
  Signal Layer 1 w20: v1(6480,3110) 6690,3320 7480,3320 7520,3280 7520,3152 7674.13,2997.87 7922.13,2997.87 7960,2960 8030,2960 8048,2978 v1(8048,3010)
  Bottom Layer w20: Q102.1@6352.6,2935.79 R122.2@6352.6,3062.64 ; R122.2@6358.5,3068.54 6358.5,3073.23 6395.28,3110 v1(6480,3110)
RELAY_RSET: J600.59
SCI_RX0: J600.76 U602.5 | length 3112
  Signal Layer 2 w10: v1(7760,460) 7780,480 7780,1290 8190,1700 8190,2827.4 8332,2969.4 v1(8332,3270)
  Bottom Layer w20: v1(7760,460) 7765,455 U602.5@7822.99,455
SCI_TX0: J600.78 U602.3 | length 3219
  Signal Layer 2 w10: v1(7760,370) 7760,377.65 7782.87,400.53 7782.87,457.6 7797.87,472.6 7797.87,1282.6 8207.87,1692.6 8207.87,2820 8363,2975.13 v1(8363,3270)
  Bottom Layer w20: v1(7760,370) 7775,355 U602.3@7822.99,355
SGND2: C616.1 J603.1 TP607.1 U602.9 U602.15 | length 1407.2
  Top Layer w50: 8671.26,263.74 J603.1@8671.26,309.61
  Signal Layer 2 w50: 8340,230 8370,260 v1(8690,260) 8720,260 ; TP607.1@8998.15,1420 TP607.1@9010,1420
  Bottom Layer w25: U602.15@8197.01,305 C616.1@8276.5,305 ; U602.9@8197.01,605 8238.27,605 8460,383.27 8460,292.84 ; C616.1@8280,301.5 8280,292.84 8460,292.84 ; v1(8690,260) 8520,260 8487.16,292.84 8460,292.84
  other v1: 8360,230 8330,240 8720,250
SWNODE1: L100.3 TP105.1 | length 696.4
  Top Layer w100: L100.3@7000,650 7000,453.45 TP105.1@7353.45,100
SWNODE2: L101.3 TP108.1 | length 1237
  Top Layer w100: L101.3@3740,660 4185,660 TP108.1@4745,100
SWNODE3: L102.3 TP111.1 | length 1387
  Top Layer w100: L102.3@1020,660 1615,660 TP111.1@2175,100
VREFHI: J600.45
pads on no net: J104.2 J600.1 J600.2 J600.3 J600.4 J600.5 J600.6 J600.8 J600.9 J600.11 J600.13 J600.14 J600.16 J600.23 J600.26 J600.27 J600.28 J600.29 J600.30 J600.31 J600.32 J600.33 J600.34 J600.36 J600.37 J600.39 J600.40 J600.41 J600.42 J600.43 J600.44 J600.66 J600.67 J600.68 J600.69 J600.70 J600.71 J600.72 J600.73 J600.75 J600.77 J600.79 J600.80 J600.81 J600.82 J600.85 J600.86 J600.87 J600.88 J600.89 J600.90 J600.91 J600.92 J600.93 J600.94 J600.95 J600.96 J600.99 J600.100 J600.101 J600.102 J600.103 J600.104 J600.105 J600.106 J600.107 J600.108 J600.109 J600.110 J600.113 J600.114 J600.115 J600.116 J600.117 J600.118 J600.119 J600.120 J600.181 J600.182 J600.185 J600.186 J601.2 J601.MP1 J601.MP2 J602.MP1 J602.MP2 J603.2 J603.MP1 J603.MP2 L102.4 U103.4 U105.4 U105.8 U105.9 U105.10 U105.14 U600.1 U602.6 U602.7 U602.10 U602.11

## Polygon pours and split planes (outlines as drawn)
AC_L on Top Layer "AC_L" (solid, remove dead copper, pour order 156): 3710,2170 3690,2150 3690,2080 3690,2060 3710,2040 3890,2040 4400,2040 4520,2160 4520,2260 4510,2270 4330,2270 4230,2170
5VS on Top Layer "5VS" (solid, remove dead copper, pour order 4): 8810,345 8800,335 8800,305 8800,255 8800,245 8810,235 8830,235 8850,235 8860,245 8860,335 8850,345
12VP on Top Layer "12VP" (solid, remove dead copper, pour order 0): 6540,2600 6530,2600 6480,2650 6450.24,2679.76 6450.24,2710 6450.24,2730.24 6460,2740 6487.99,2740 6600,2740 6610,2730 6610,2710 6610,2610 6600,2600
NetD106_1 on Top Layer "D106_1" (solid, remove dead copper, pour order 2): 21 vertices, not listed, extent 6450,2780 6610,2930.5
NetC109_2 on Top Layer "C109_2" (solid, remove dead copper, pour order 6): 17 vertices, not listed, extent 50,2870 1500,3300
NetC110_2 on Top Layer "C110_2" (solid, remove dead copper, pour order 18): 1970,3020 1960,3030 1960,3050 1960,3160 2020,3220 2100,3300 2140,3300 3100,3300 3240,3160 3240,3130 3240,3030 3230,3020
AC_N on Top Layer "AC_N" (solid, remove dead copper, pour order 44): 23 vertices, not listed, extent 4870,2030 6410,2620
-BRDG_N on Top Layer "-BRDG_N" (solid, remove dead copper, pour order 56): 5850,2010 5840,2000 5840,1970 5840,1860 5840,1710 5850,1700 5860,1700 5930,1700 5940,1710 5940,1730 5940,1810 5990,1860 5990,2000 5980,2010
NetF100_2 on Top Layer "F100_2" (solid, remove dead copper, pour order 70): 50,2000 110,1940 330,1940 360,1940 500,2080 500,2120 500,2200 470,2230 420,2230 160,2230 50,2120
NetC109_1 on Top Layer "C109_1" (solid, remove dead copper, pour order 82): 18 vertices, not listed, extent 140,2040 1500,2630
NetC107_1 on Top Layer "C107_1" (solid, remove dead copper, pour order 96): 1960,1950 1970,1940 3230,1940 3240,1950 3240,2130 3100,2270 3050,2270 2550,2270 2460,2180 2270,2180 1970,2180 1960,2170
EARTH on Top Layer "Earth" (solid, remove dead copper, pour order 110): 25 vertices, not listed, extent 530,2390 4140,2850
NetC113_1 on Top Layer "C113_2" (solid, remove dead copper, pour order 178): 3700,3020 3690,3030 3690,3160 3830,3300 4340,3300 4400,3300 4460,3240 4620,3080 4620,2660 4600,2640 4560,2640 4430,2770 4180,3020 3710,3020
NetC113_1 on Top Layer "C113_2" (solid, remove dead copper, pour order 186): 4890,2640 4870,2660 4870,2680 4870,2860 4890,2880 4920,2880 5480,2880 5800,2880 5870,2810 5870,2660 5850,2640
SWNODE3 on Top Layer "SWNODE3" (solid, remove dead copper, pour order 204): 970,770 950,750 950,700 950,640 950,560 970,540 1530,540 2030,40 2050,40 2220,40 2240,60 2240,80 2240,230 1700,770 1250,770
SWNODE2 on Top Layer "SWNODE2" (solid, remove dead copper, pour order 208): 3690,520 3670,540 3670,660 3670,730 3690,750 3730,750 4420,750 4810,360 4810,50 4790,30 4760,30 4680,30 4190,520
SWNODE1 on Top Layer "SWNODE1" (solid, remove dead copper, pour order 212): 6890,710 6870,690 6870,660 6870,470 7300,40 7400,40 7420,60 7420,80 7420,320 7030,710
EARTH on Top Layer "EARTH" (solid, remove dead copper, pour order 236): 18 vertices, not listed, extent 10,780 670,1850
PGND on Top Layer "PGND" (solid, remove dead copper, pour order 240): 68 vertices, not listed, extent 260,20 9630,3330
EARTH on Top Layer "EARTH" (solid, remove dead copper, pour order 256): 9290,2740 9290,2070 9310,2050 9620,2050 9640,2070 9640,2090 9640,2470 9640,2740 9620,2760 9310,2760
NetL102_1 on Top Layer "L102_1" (solid, remove dead copper, pour order 194): 1770,1200.32 1750,1220.32 1750,1230.32 1750,1260.32 1750,1400 1770,1420 1930,1420 1980,1370 1980,1220.32 1960,1200.32
NetL101_1 on Top Layer "L101_1" (solid, remove dead copper, pour order 190): 4500,1190 4480,1210 4480,1230 4480,1370 4500,1390 4630,1390 4700,1320 4700,1210 4680,1190
NetL100_1 on Top Layer "L100_1" (solid, remove dead copper, pour order 188): 6430,1270 6450,1290 6450,1340 6450,1430 6450,1490 6470,1510 6470,1590 6450,1610 6350,1610 6330,1610 6260,1540 6260,1290 6280,1270
NetC109_2 on Signal Layer 1 "C109_2" (solid, remove dead copper, pour order 12): 17 vertices, not listed, extent 50,2870 1500,3300
NetC110_2 on Signal Layer 1 "C110_2" (solid, remove dead copper, pour order 30): 1970,3020 1960,3030 1960,3050 1960,3160 2020,3220 2100,3300 2140,3300 3100,3300 3240,3160 3240,3130 3240,3030 3230,3020
-BRDG_N on Signal Layer 1 "-BRDG_N" (solid, remove dead copper, pour order 58): 5850,2010 5840,2000 5840,1970 5840,1860 5840,1710 5850,1700 5860,1700 5930,1700 5940,1710 5940,1730 5940,1810 5990,1860 5990,2000 5980,2010
NetF100_2 on Signal Layer 1 "F100_2" (solid, remove dead copper, pour order 80): 50,2000 110,1940 330,1940 360,1940 500,2080 500,2120 500,2200 470,2230 420,2230 160,2230 50,2120
NetC109_1 on Signal Layer 1 "C109_1" (solid, remove dead copper, pour order 94): 18 vertices, not listed, extent 140,2040 1500,2630
NetC107_1 on Signal Layer 1 "C107_1" (solid, remove dead copper, pour order 108): 1960,1950 1970,1940 3230,1940 3240,1950 3240,2130 3100,2270 3050,2270 2550,2270 2460,2180 2270,2180 1970,2180 1960,2170
EARTH on Signal Layer 1 "Earth" (solid, remove dead copper, pour order 120): 25 vertices, not listed, extent 530,2390 4140,2850
NetC113_1 on Signal Layer 1 "C113_2" (solid, remove dead copper, pour order 174): 3700,3020 3690,3030 3690,3060 3690,3160 3830,3300 4405.28,3300 4825.28,2880 5800,2880 5870,2810 5870,2780 5870,2660 5850,2640 5620,2640 4560,2640 4180,3020
AC_N on Signal Layer 1 "AC_N" (solid, remove dead copper, pour order 184): 23 vertices, not listed, extent 4870,2030 6410,2620
HVBUS on Signal Layer 1 "HVBUS" (solid, remove dead copper, pour order 216): 89 vertices, not listed, extent 1690,30 9625,1810
PGND on Signal Layer 1 "PGND" (solid, remove dead copper, pour order 250): 65 vertices, not listed, extent 260,20 9630,3330
NetL102_1 on Signal Layer 1 "L102_1" (solid, remove dead copper, pour order 218): 1770,1200.32 1750,1220.32 1750,1230.32 1750,1260.32 1750,1400 1770,1420 1930,1420 1980,1370 1980,1220.32 1960,1200.32
NetL101_1 on Signal Layer 1 "L101_1" (solid, remove dead copper, pour order 226): 4500,1190 4480,1210 4480,1230 4480,1370 4500,1390 4630,1390 4700,1320 4700,1210 4680,1190
NetL100_1 on Signal Layer 1 "L100_1" (solid, remove dead copper, pour order 210): 6430,1270 6450,1290 6450,1340 6450,1430 6450,1490 6470,1510 6470,1590 6450,1610 6350,1610 6330,1610 6260,1540 6260,1290 6280,1270
SGND2 on Signal Layer 2 "SGND2" (solid, remove dead copper, pour order 258): 29 vertices, not listed, extent 8310,200 9060,1480
NetC109_2 on Signal Layer 2 "C109_2" (solid, remove dead copper, pour order 14): 17 vertices, not listed, extent 50,2870 1500,3300
NetC110_2 on Signal Layer 2 "C110_2" (solid, remove dead copper, pour order 28): 1970,3020 1960,3030 1960,3050 1960,3160 2020,3220 2100,3300 2140,3300 3100,3300 3240,3160 3240,3130 3240,3030 3230,3020
AC_N on Signal Layer 2 "AC_N" (solid, remove dead copper, pour order 48): 4890,2620 4870,2600 4870,2450 4890,2430 5400,2430 5450,2480 5450,2610 5440,2620
-BRDG_N on Signal Layer 2 "-BRDG_N" (solid, remove dead copper, pour order 60): 29 vertices, not listed, extent 5400,1380 5990,2010
AC_N on Signal Layer 2 "AC_N" (solid, remove dead copper, pour order 62): 5980,2030 5990,2040 5990,2060 5990,2205.04 5990,2250 5910,2330 5900,2330 5770,2330 5750,2310 5750,2260 5820,2190 5840,2170 5840,2120 5840,2040 5850,2030
NetF100_2 on Signal Layer 2 "F100_2" (solid, remove dead copper, pour order 78): 50,2000 110,1940 330,1940 360,1940 500,2080 500,2120 500,2200 470,2230 420,2230 160,2230 50,2120
NetC109_1 on Signal Layer 2 "C109_1" (solid, remove dead copper, pour order 92): 18 vertices, not listed, extent 140,2040 1500,2630
NetC107_1 on Signal Layer 2 "C107_1" (solid, remove dead copper, pour order 106): 1960,1950 1970,1940 3230,1940 3240,1950 3240,2130 3100,2270 3050,2270 2550,2270 2460,2180 2270,2180 1970,2180 1960,2170
EARTH on Signal Layer 2 "Earth" (solid, remove dead copper, pour order 118): 25 vertices, not listed, extent 530,2390 4140,2850
NetC113_1 on Signal Layer 2 "C113_2" (solid, remove dead copper, pour order 172): 3700,3020 3690,3030 3690,3060 3690,3160 3830,3300 4405.28,3300 4825.28,2880 5800,2880 5870,2810 5870,2780 5870,2660 5850,2640 5620,2640 4560,2640 4180,3020
NetL100_1 on Signal Layer 2 "L100_1" (solid, remove dead copper, pour order 200): 6430,1270 6450,1290 6450,1340 6450,1430 6450,1490 6470,1510 6470,1590 6450,1610 6350,1610 6330,1610 6260,1540 6260,1290 6280,1270
AC_L on Signal Layer 2 "AC_L" (solid, remove dead copper, pour order 202): 66 vertices, not listed, extent 1440,1020 6450,2270
PGND on Signal Layer 2 "PGND" (solid, remove dead copper, pour order 248): 56 vertices, not listed, extent 260,20 9060,3330
NetL102_1 on Signal Layer 2 "L102_1" (solid, remove dead copper, pour order 196): 1770,1200.32 1750,1220.32 1750,1230.32 1750,1260.32 1750,1400 1770,1420 1930,1420 1980,1370 1980,1220.32 1960,1200.32
NetL101_1 on Signal Layer 2 "L101_1" (solid, remove dead copper, pour order 198): 4500,1190 4480,1210 4480,1230 4480,1370 4500,1390 4630,1390 4700,1320 4700,1210 4680,1190
NetC109_2 on Signal Layer 3 "C109_2" (solid, remove dead copper, pour order 10): 17 vertices, not listed, extent 50,2870 1500,3300
NetC110_2 on Signal Layer 3 "C110_2" (solid, remove dead copper, pour order 26): 1970,3020 1960,3030 1960,3050 1960,3160 2020,3220 2100,3300 2140,3300 3100,3300 3240,3160 3240,3130 3240,3030 3230,3020
-BRDG_N on Signal Layer 3 "-BRDG_N" (solid, remove dead copper, pour order 68): 29 vertices, not listed, extent 5400,1380 5990,2010
NetF100_2 on Signal Layer 3 "F100_2" (solid, remove dead copper, pour order 76): 50,2000 110,1940 330,1940 360,1940 500,2080 500,2120 500,2200 470,2230 420,2230 160,2230 50,2120
NetC109_1 on Signal Layer 3 "C109_1" (solid, remove dead copper, pour order 90): 18 vertices, not listed, extent 140,2040 1500,2630
NetC107_1 on Signal Layer 3 "C107_1" (solid, remove dead copper, pour order 104): 1960,1950 1970,1940 3230,1940 3240,1950 3240,2130 3100,2270 3050,2270 2550,2270 2460,2180 2270,2180 1970,2180 1960,2170
EARTH on Signal Layer 3 "Earth" (solid, remove dead copper, pour order 116): 25 vertices, not listed, extent 530,2390 4140,2850
NetC113_1 on Signal Layer 3 "C113_2" (solid, remove dead copper, pour order 170): 3700,3020 3690,3030 3690,3060 3690,3160 3830,3300 4405.28,3300 4825.28,2880 5800,2880 5870,2810 5870,2780 5870,2660 5850,2640 5620,2640 4560,2640 4180,3020
AC_N on Signal Layer 3 "AC_N" (solid, remove dead copper, pour order 182): 23 vertices, not listed, extent 4870,2030 6410,2620
PGND on Signal Layer 3 "PGND" (solid, remove dead copper, pour order 252): 67 vertices, not listed, extent 260,20 9630,3330
NetL102_1 on Signal Layer 3 "L102_1" (solid, remove dead copper, pour order 232): 1770,1200.32 1750,1220.32 1750,1230.32 1750,1260.32 1750,1400 1770,1420 1930,1420 1980,1370 1980,1220.32 1960,1200.32
NetL101_1 on Signal Layer 3 "L101_1" (solid, remove dead copper, pour order 224): 4500,1190 4480,1210 4480,1230 4480,1370 4500,1390 4630,1390 4700,1320 4700,1210 4680,1190
NetL100_1 on Signal Layer 3 "L100_1" (solid, remove dead copper, pour order 230): 6430,1270 6450,1290 6450,1340 6450,1430 6450,1490 6470,1510 6470,1590 6450,1610 6350,1610 6330,1610 6260,1540 6260,1290 6280,1270
NetC109_2 on Signal Layer 4 "C109_2" (solid, remove dead copper, pour order 8): 17 vertices, not listed, extent 51.09,2870 1501.09,3300
NetC110_2 on Signal Layer 4 "C110_2" (solid, remove dead copper, pour order 24): 1970,3020 1960,3030 1960,3050 1960,3160 2020,3220 2100,3300 2140,3300 3100,3300 3240,3160 3240,3130 3240,3030 3230,3020
NetF100_2 on Signal Layer 4 "F100_2" (solid, remove dead copper, pour order 74): 50,2000 110,1940 330,1940 360,1940 500,2080 500,2120 500,2200 470,2230 420,2230 160,2230 50,2120
NetC109_1 on Signal Layer 4 "C109_1" (solid, remove dead copper, pour order 86): 18 vertices, not listed, extent 140,2040 1500,2630
NetC107_1 on Signal Layer 4 "C107_1" (solid, remove dead copper, pour order 102): 1960,1950 1970,1940 3230,1940 3240,1950 3240,2130 3100,2270 3050,2270 2550,2270 2460,2180 2270,2180 1970,2180 1960,2170
EARTH on Signal Layer 4 "Earth" (solid, remove dead copper, pour order 114): 25 vertices, not listed, extent 530,2390 4140,2850
NetC113_1 on Signal Layer 4 "C113_2" (solid, remove dead copper, pour order 168): 17 vertices, not listed, extent 3690,2640 5870,3300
